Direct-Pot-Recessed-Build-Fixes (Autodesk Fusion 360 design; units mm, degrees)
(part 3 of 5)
sketch "Restore cam service opening after obsolete bore closure" plane through (23.9, 0, 0) normal (1, 0, 0) x axis (0, 0, -1)
  line L1 (-42.2047, 46.7373) -> (-43.8497, 47.5044)
  line L2 (-40.5875, 45.9133) -> (-42.2047, 46.7373)
  line L3 (-39, 45.0333) -> (-40.5875, 45.9133)
  line L4 (-37.4442, 44.0985) -> (-39, 45.0333)
  line L5 (-35.922, 43.11) -> (-37.4442, 44.0985)
  line L6 (-34.4352, 42.0689) -> (-35.922, 43.11)
  line L7 (-32.9856, 40.9766) -> (-34.4352, 42.0689)
  line L8 (-31.575, 39.8343) -> (-32.9856, 40.9766)
  line L9 (-30.2052, 38.6435) -> (-31.575, 39.8343)
  line L10 (-28.8778, 37.4057) -> (-30.2052, 38.6435)
  line L11 (-27.5943, 36.1222) -> (-28.8778, 37.4057)
  line L12 (-26.3565, 34.7948) -> (-27.5943, 36.1222)
  line L13 (-25.1657, 33.425) -> (-26.3565, 34.7948)
  line L14 (-24.0234, 32.0144) -> (-25.1657, 33.425)
  line L15 (-22.9311, 30.5648) -> (-24.0234, 32.0144)
  line L16 (-21.89, 29.078) -> (-22.9311, 30.5648)
  line L17 (-20.9015, 27.5558) -> (-21.89, 29.078)
  line L18 (-19.9667, 26) -> (-20.9015, 27.5558)
  line L19 (-19.0867, 24.4125) -> (-19.9667, 26)
  line L20 (-18.2627, 22.7953) -> (-19.0867, 24.4125)
  line L21 (-17.4956, 21.1503) -> (-18.2627, 22.7953)
  line L22 (-16.7864, 19.4795) -> (-17.4956, 21.1503)
  line L23 (-16.136, 17.785) -> (-16.7864, 19.4795)
  line L24 (-15.5451, 16.0689) -> (-16.136, 17.785)
  line L25 (-15.0144, 14.3331) -> (-15.5451, 16.0689)
  line L26 (-14.5446, 12.5799) -> (-15.0144, 14.3331)
  line L27 (-14.1363, 10.8114) -> (-14.5446, 12.5799)
  line L28 (-13.79, 9.0297) -> (-14.1363, 10.8114)
  line L29 (-13.5061, 7.237) -> (-13.79, 9.0297)
  line L30 (-13.2849, 5.4355) -> (-13.5061, 7.237)
  line L31 (-13.1267, 3.6273) -> (-13.2849, 5.4355)
  line L32 (-13.0317, 1.8148) -> (-13.1267, 3.6273)
  line L33 (-13, 0) -> (-13.0317, 1.8148)
  line L34 (-13.0317, -1.8148) -> (-13, 0)
  line L35 (-13.1267, -3.6273) -> (-13.0317, -1.8148)
  line L36 (-13.2849, -5.4355) -> (-13.1267, -3.6273)
  line L37 (-13.5061, -7.237) -> (-13.2849, -5.4355)
  line L38 (-13.79, -9.0297) -> (-13.5061, -7.237)
  line L39 (-14.1363, -10.8114) -> (-13.79, -9.0297)
  line L40 (-14.5446, -12.5799) -> (-14.1363, -10.8114)
  line L41 (-15.0144, -14.3331) -> (-14.5446, -12.5799)
  line L42 (-15.5451, -16.0689) -> (-15.0144, -14.3331)
  line L43 (-16.136, -17.785) -> (-15.5451, -16.0689)
  line L44 (-16.7864, -19.4795) -> (-16.136, -17.785)
  line L45 (-17.4956, -21.1503) -> (-16.7864, -19.4795)
  line L46 (-18.2627, -22.7953) -> (-17.4956, -21.1503)
  line L47 (-19.0867, -24.4125) -> (-18.2627, -22.7953)
  line L48 (-19.9667, -26) -> (-19.0867, -24.4125)
  line L49 (-20.9015, -27.5558) -> (-19.9667, -26)
  line L50 (-21.89, -29.078) -> (-20.9015, -27.5558)
  line L51 (-22.9311, -30.5648) -> (-21.89, -29.078)
  line L52 (-24.0234, -32.0144) -> (-22.9311, -30.5648)
  line L53 (-25.1657, -33.425) -> (-24.0234, -32.0144)
  line L54 (-26.3565, -34.7948) -> (-25.1657, -33.425)
  line L55 (-27.5943, -36.1222) -> (-26.3565, -34.7948)
  line L56 (-28.8778, -37.4057) -> (-27.5943, -36.1222)
  line L57 (-30.2052, -38.6435) -> (-28.8778, -37.4057)
  line L58 (-31.575, -39.8343) -> (-30.2052, -38.6435)
  line L59 (-32.9856, -40.9766) -> (-31.575, -39.8343)
  line L60 (-34.4352, -42.0689) -> (-32.9856, -40.9766)
  line L61 (-35.922, -43.11) -> (-34.4352, -42.0689)
  line L62 (-37.4442, -44.0985) -> (-35.922, -43.11)
  line L63 (-39, -45.0333) -> (-37.4442, -44.0985)
  line L64 (-40.5875, -45.9133) -> (-39, -45.0333)
  line L65 (-42.2047, -46.7373) -> (-40.5875, -45.9133)
  line L66 (-43.8497, -47.5044) -> (-42.2047, -46.7373)
  line L67 (-54.4248, -23.7522) -> (-43.8497, -47.5044)
  line L68 (-53.6024, -23.3686) -> (-54.4248, -23.7522)
  line L69 (-52.7937, -22.9566) -> (-53.6024, -23.3686)
  line L70 (-52, -22.5167) -> (-52.7937, -22.9566)
  line L71 (-51.2221, -22.0493) -> (-52, -22.5167)
  line L72 (-50.461, -21.555) -> (-51.2221, -22.0493)
  line L73 (-49.7176, -21.0344) -> (-50.461, -21.555)
  line L74 (-48.9928, -20.4883) -> (-49.7176, -21.0344)
  line L75 (-48.2875, -19.9172) -> (-48.9928, -20.4883)
  line L76 (-47.6026, -19.3218) -> (-48.2875, -19.9172)
  line L77 (-46.9389, -18.7028) -> (-47.6026, -19.3218)
  line L78 (-46.2972, -18.0611) -> (-46.9389, -18.7028)
  line L79 (-45.6782, -17.3974) -> (-46.2972, -18.0611)
  line L80 (-45.0828, -16.7125) -> (-45.6782, -17.3974)
  line L81 (-44.5117, -16.0072) -> (-45.0828, -16.7125)
  line L82 (-43.9656, -15.2824) -> (-44.5117, -16.0072)
  line L83 (-43.445, -14.539) -> (-43.9656, -15.2824)
  line L84 (-42.9507, -13.7779) -> (-43.445, -14.539)
  line L85 (-42.4833, -13) -> (-42.9507, -13.7779)
  line L86 (-42.0434, -12.2063) -> (-42.4833, -13)
  line L87 (-41.6314, -11.3976) -> (-42.0434, -12.2063)
  line L88 (-41.2478, -10.5752) -> (-41.6314, -11.3976)
  line L89 (-40.8932, -9.7398) -> (-41.2478, -10.5752)
  line L90 (-40.568, -8.8925) -> (-40.8932, -9.7398)
  line L91 (-40.2725, -8.0344) -> (-40.568, -8.8925)
  line L92 (-40.0072, -7.1666) -> (-40.2725, -8.0344)
  line L93 (-39.7723, -6.29) -> (-40.0072, -7.1666)
  line L94 (-39.5682, -5.4057) -> (-39.7723, -6.29)
  line L95 (-39.395, -4.5149) -> (-39.5682, -5.4057)
  line L96 (-39.253, -3.6185) -> (-39.395, -4.5149)
  line L97 (-39.1424, -2.7177) -> (-39.253, -3.6185)
  line L98 (-39.0633, -1.8137) -> (-39.1424, -2.7177)
  line L99 (-39.0158, -0.9074) -> (-39.0633, -1.8137)
  line L100 (-39, 0) -> (-39.0158, -0.9074)
  line L101 (-39.0158, 0.9074) -> (-39, 0)
  line L102 (-39.0633, 1.8137) -> (-39.0158, 0.9074)
  line L103 (-39.1424, 2.7177) -> (-39.0633, 1.8137)
  line L104 (-39.253, 3.6185) -> (-39.1424, 2.7177)
  line L105 (-39.395, 4.5149) -> (-39.253, 3.6185)
  line L106 (-39.5682, 5.4057) -> (-39.395, 4.5149)
  line L107 (-39.7723, 6.29) -> (-39.5682, 5.4057)
  line L108 (-40.0072, 7.1666) -> (-39.7723, 6.29)
  line L109 (-40.2725, 8.0344) -> (-40.0072, 7.1666)
  line L110 (-40.568, 8.8925) -> (-40.2725, 8.0344)
  line L111 (-40.8932, 9.7398) -> (-40.568, 8.8925)
  line L112 (-41.2478, 10.5752) -> (-40.8932, 9.7398)
  line L113 (-41.6314, 11.3976) -> (-41.2478, 10.5752)
  line L114 (-42.0434, 12.2063) -> (-41.6314, 11.3976)
  line L115 (-42.4833, 13) -> (-42.0434, 12.2063)
  line L116 (-42.9507, 13.7779) -> (-42.4833, 13)
  line L117 (-43.445, 14.539) -> (-42.9507, 13.7779)
  line L118 (-43.9656, 15.2824) -> (-43.445, 14.539)
  line L119 (-44.5117, 16.0072) -> (-43.9656, 15.2824)
  line L120 (-45.0828, 16.7125) -> (-44.5117, 16.0072)
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extrude "Extrude47" cut sketch "Restore cam service opening after obsolete bore closure" along normal blind 12.2
work_plane "WorkPlane48" AlongDistance -15.4 ExtraOffset 0
sketch "Fill former M5 stop nut pocket" plane through (-15.4, 0, 0) normal (1, 0, 0) x axis (0, 0, -1)
  circle C1 centre (-79.6754, -33.9652) radius 4.9
extrude "Extrude48" add sketch "Fill former M5 stop nut pocket" along normal blind 6.4
work_plane "WorkPlane49" AlongDistance -36 ExtraOffset 0
sketch "Fill former M5 stop bore" plane through (-36, 0, 0) normal (1, 0, 0) x axis (0, 0, -1)
  circle C1 centre (-79.6754, -33.9652) radius 2.71
extrude "Extrude49" add sketch "Fill former M5 stop bore" along normal blind 27
work_plane "WorkPlane50" AlongDistance -36.1 ExtraOffset 0
sketch "M3 stop reinforcement bore" plane through (-36.1, 0, 0) normal (1, 0, 0) x axis (0, 0, -1)
  circle C1 centre (-79.6754, -33.9652) radius 1.7
extrude "Extrude50" cut sketch "M3 stop reinforcement bore" along normal blind 27.2
work_plane "WorkPlane51" AlongDistance -13.5 ExtraOffset 0
sketch "Captive M3 locknut stop pocket" plane through (-13.5, 0, 0) normal (1, 0, 0) x axis (0, 0, -1)
  line L1 (-82.5754, -32.2908) -> (-79.6754, -30.6165)
  line L2 (-82.5754, -35.6395) -> (-82.5754, -32.2908)
  line L3 (-79.6754, -37.3138) -> (-82.5754, -35.6395)
  line L4 (-76.7754, -35.6395) -> (-79.6754, -37.3138)
  line L5 (-76.7754, -32.2908) -> (-76.7754, -35.6395)
  line L6 (-79.6754, -30.6165) -> (-76.7754, -32.2908)
extrude "Extrude51" cut sketch "Captive M3 locknut stop pocket" along normal blind 4.6
work_plane "WorkPlane52" AlongDistance -15.4 ExtraOffset 0
sketch "Fill former M5 stop nut pocket (1)" plane through (-15.4, 0, 0) normal (1, 0, 0) x axis (0, 0, -1)
  circle C1 centre (-79.6754, 33.9652) radius 4.9
extrude "Extrude52" add sketch "Fill former M5 stop nut pocket (1)" along normal blind 6.4
work_plane "WorkPlane53" AlongDistance -36 ExtraOffset 0
sketch "Fill former M5 stop bore (1)" plane through (-36, 0, 0) normal (1, 0, 0) x axis (0, 0, -1)
  circle C1 centre (-79.6754, 33.9652) radius 2.71
extrude "Extrude53" add sketch "Fill former M5 stop bore (1)" along normal blind 27
work_plane "WorkPlane54" AlongDistance -36.1 ExtraOffset 0
sketch "M3 stop reinforcement bore (1)" plane through (-36.1, 0, 0) normal (1, 0, 0) x axis (0, 0, -1)
  circle C1 centre (-79.6754, 33.9652) radius 1.7
extrude "Extrude54" cut sketch "M3 stop reinforcement bore (1)" along normal blind 27.2
work_plane "WorkPlane55" AlongDistance -13.5 ExtraOffset 0
sketch "Captive M3 locknut stop pocket (1)" plane through (-13.5, 0, 0) normal (1, 0, 0) x axis (0, 0, -1)
  line L1 (-82.5754, 35.6395) -> (-79.6754, 37.3138)
  line L2 (-82.5754, 32.2908) -> (-82.5754, 35.6395)
  line L3 (-79.6754, 30.6165) -> (-82.5754, 32.2908)
  line L4 (-76.7754, 32.2908) -> (-79.6754, 30.6165)
  line L5 (-76.7754, 35.6395) -> (-76.7754, 32.2908)
  line L6 (-79.6754, 37.3138) -> (-76.7754, 35.6395)
extrude "Extrude55" cut sketch "Captive M3 locknut stop pocket (1)" along normal blind 4.6
work_plane "WorkPlane56" AlongDistance -17.5 ExtraOffset 0
sketch "Recess M3 locknut to keep bolt inside stop" plane through (-17.5, 0, 0) normal (1, 0, 0) x axis (0, 0, -1)
  line L1 (-82.5754, -32.2908) -> (-79.6754, -30.6165)
  line L2 (-82.5754, -35.6395) -> (-82.5754, -32.2908)
  line L3 (-79.6754, -37.3138) -> (-82.5754, -35.6395)
  line L4 (-76.7754, -35.6395) -> (-79.6754, -37.3138)
  line L5 (-76.7754, -32.2908) -> (-76.7754, -35.6395)
  line L6 (-79.6754, -30.6165) -> (-76.7754, -32.2908)
extrude "Extrude56" cut sketch "Recess M3 locknut to keep bolt inside stop" along normal blind 4.01
work_plane "WorkPlane57" AlongDistance -17.5 ExtraOffset 0
sketch "Recess M3 locknut to keep bolt inside stop (1)" plane through (-17.5, 0, 0) normal (1, 0, 0) x axis (0, 0, -1)
  line L1 (-82.5754, 35.6395) -> (-79.6754, 37.3138)
  line L2 (-82.5754, 32.2908) -> (-82.5754, 35.6395)
  line L3 (-79.6754, 30.6165) -> (-82.5754, 32.2908)
  line L4 (-76.7754, 32.2908) -> (-79.6754, 30.6165)
  line L5 (-76.7754, 35.6395) -> (-76.7754, 32.2908)
  line L6 (-79.6754, 37.3138) -> (-76.7754, 35.6395)
extrude "Extrude57" cut sketch "Recess M3 locknut to keep bolt inside stop (1)" along normal blind 4.01
work_plane "WorkPlane6" AlongDistance -7.2 ExtraOffset 0
sketch "Upright socket roof 45 degrees" plane through (0, -7.2, 0) normal (0, 1, 0) x axis (1, 0, 0)
  line L1 (-7.2, -196) -> (0, -196)
  line L2 (0, -203.2) -> (-7.2, -196)
  line L3 (0, -196) -> (0, -203.2)
extrude "Extrude5" cut sketch "Upright socket roof 45 degrees" along normal blind 14.4
work_plane "WorkPlane8" AlongDistance -7.2 ExtraOffset 0
sketch "Upright socket roof 45 degrees" plane through (0, -7.2, 0) normal (0, 1, 0) x axis (1, 0, 0)
  line L1 (7.2, -196) -> (0, -196)
  line L2 (0, -203.2) -> (7.2, -196)
  line L3 (0, -196) -> (0, -203.2)
extrude "Extrude7" cut sketch "Upright socket roof 45 degrees" along normal blind 14.4
work_plane "WorkPlane58" AlongDistance -36 ExtraOffset 0
sketch "Stock M5x14 mounting seat Z64" plane through (-36, 0, 0) normal (1, 0, 0) x axis (0, 0, -1)
  line L1 (-63, -70) -> (-63, -95)
  line L2 (-64, -70) -> (-63, -70)
  line L3 (-64, -95) -> (-64, -70)
  line L4 (-63, -95) -> (-64, -95)
extrude "Extrude58" add sketch "Stock M5x14 mounting seat Z64" along normal blind 12
work_plane "WorkPlane59" AlongDistance 62.9 ExtraOffset 0
sketch "Continue rail clearance through new seat" plane through (0, 0, 62.9) normal (0, 0, 1) x axis (1, 0, 0)
  circle C1 centre (-30, -85) radius 2.7
extrude "Extrude59" cut sketch "Continue rail clearance through new seat" along normal blind 1.2
work_plane "WorkPlane1" AlongDistance 50 ExtraOffset 0
sketch "Rail M5x14 DIN912 (-30, -1)" plane through (0, 0, 50) normal (0, 0, 1) x axis (1, 0, 0)
  circle C1 centre (-30, -85) radius 2.5
extrude "Extrude1" new body sketch "Rail M5x14 DIN912 (-30, -1)" along normal blind 14 bodies "HARDWARE Rail M5x14 DIN912 (-30, -1)"
work_plane "WorkPlane2" AlongDistance 64 ExtraOffset 0
sketch "Button head" plane through (0, 0, 64) normal (0, 0, 1) x axis (1, 0, 0)
  circle C1 centre (-30, -85) radius 4.25
extrude "Extrude2" add sketch "Button head" along normal blind 5
work_plane "WorkPlane60" AlongDistance -36 ExtraOffset 0
sketch "Stock M5x14 mounting seat Z64 (1)" plane through (-36, 0, 0) normal (1, 0, 0) x axis (0, 0, -1)
  line L1 (-63, 95) -> (-63, 70)
  line L2 (-64, 95) -> (-63, 95)
  line L3 (-64, 70) -> (-64, 95)
  line L4 (-63, 70) -> (-64, 70)
extrude "Extrude60" add sketch "Stock M5x14 mounting seat Z64 (1)" along normal blind 12
work_plane "WorkPlane61" AlongDistance 62.9 ExtraOffset 0
sketch "Continue rail clearance through new seat (1)" plane through (0, 0, 62.9) normal (0, 0, 1) x axis (1, 0, 0)
  circle C1 centre (-30, 85) radius 2.7
extrude "Extrude61" cut sketch "Continue rail clearance through new seat (1)" along normal blind 1.2
work_plane "WorkPlane1" AlongDistance 50 ExtraOffset 0
sketch "Rail M5x14 DIN912 (-30, 1)" plane through (0, 0, 50) normal (0, 0, 1) x axis (1, 0, 0)
  circle C1 centre (-30, 85) radius 2.5
extrude "Extrude1" new body sketch "Rail M5x14 DIN912 (-30, 1)" along normal blind 14 bodies "HARDWARE Rail M5x14 DIN912 (-30, 1)"
work_plane "WorkPlane2" AlongDistance 64 ExtraOffset 0
sketch "Button head" plane through (0, 0, 64) normal (0, 0, 1) x axis (1, 0, 0)
  circle C1 centre (-30, 85) radius 4.25
extrude "Extrude2" add sketch "Button head" along normal blind 5
work_plane "WorkPlane62" AlongDistance -36 ExtraOffset 0
sketch "Close obsolete long pivot screw hole" plane through (-36, 0, 0) normal (1, 0, 0) x axis (0, 0, -1)
  circle C1 centre (-12, -35) radius 1.71
extrude "Extrude62" add sketch "Close obsolete long pivot screw hole" along normal blind 12
work_plane "WorkPlane63" AlongDistance -26 ExtraOffset 0
sketch "Blind captive printed pivot seat" plane through (-26, 0, 0) normal (1, 0, 0) x axis (0, 0, -1)
  circle C1 centre (-12, -35) radius 4.15
extrude "Extrude63" cut sketch "Blind captive printed pivot seat" along normal blind 2.1
work_plane "WorkPlane48" AlongDistance 24 ExtraOffset 0
sketch "Stock M5x14 mounting seat Z64" plane through (24, 0, 0) normal (1, 0, 0) x axis (0, 0, -1)
  line L1 (-63, -70) -> (-63, -95)
  line L2 (-64, -70) -> (-63, -70)
  line L3 (-64, -95) -> (-64, -70)
  line L4 (-63, -95) -> (-64, -95)
extrude "Extrude48" add sketch "Stock M5x14 mounting seat Z64" along normal blind 12
work_plane "WorkPlane49" AlongDistance 62.9 ExtraOffset 0
sketch "Continue rail clearance through new seat" plane through (0, 0, 62.9) normal (0, 0, 1) x axis (1, 0, 0)
  circle C1 centre (30, -85) radius 2.7
extrude "Extrude49" cut sketch "Continue rail clearance through new seat" along normal blind 1.2
work_plane "WorkPlane1" AlongDistance 50 ExtraOffset 0
sketch "Rail M5x14 DIN912 (30, -1)" plane through (0, 0, 50) normal (0, 0, 1) x axis (1, 0, 0)
  circle C1 centre (30, -85) radius 2.5
extrude "Extrude1" new body sketch "Rail M5x14 DIN912 (30, -1)" along normal blind 14 bodies "HARDWARE Rail M5x14 DIN912 (30, -1)"
work_plane "WorkPlane2" AlongDistance 64 ExtraOffset 0
sketch "Button head" plane through (0, 0, 64) normal (0, 0, 1) x axis (1, 0, 0)
  circle C1 centre (30, -85) radius 4.25
extrude "Extrude2" add sketch "Button head" along normal blind 5
work_plane "WorkPlane50" AlongDistance 24 ExtraOffset 0
sketch "Stock M5x14 mounting seat Z64 (1)" plane through (24, 0, 0) normal (1, 0, 0) x axis (0, 0, -1)
  line L1 (-63, 95) -> (-63, 70)
  line L2 (-64, 95) -> (-63, 95)
  line L3 (-64, 70) -> (-64, 95)
  line L4 (-63, 70) -> (-64, 70)
extrude "Extrude50" add sketch "Stock M5x14 mounting seat Z64 (1)" along normal blind 12
work_plane "WorkPlane51" AlongDistance 62.9 ExtraOffset 0
sketch "Continue rail clearance through new seat (1)" plane through (0, 0, 62.9) normal (0, 0, 1) x axis (1, 0, 0)
  circle C1 centre (30, 85) radius 2.7
extrude "Extrude51" cut sketch "Continue rail clearance through new seat (1)" along normal blind 1.2
work_plane "WorkPlane1" AlongDistance 50 ExtraOffset 0
sketch "Rail M5x14 DIN912 (30, 1)" plane through (0, 0, 50) normal (0, 0, 1) x axis (1, 0, 0)
  circle C1 centre (30, 85) radius 2.5
extrude "Extrude1" new body sketch "Rail M5x14 DIN912 (30, 1)" along normal blind 14 bodies "HARDWARE Rail M5x14 DIN912 (30, 1)"
work_plane "WorkPlane2" AlongDistance 64 ExtraOffset 0
sketch "Button head" plane through (0, 0, 64) normal (0, 0, 1) x axis (1, 0, 0)
  circle C1 centre (30, 85) radius 4.25
extrude "Extrude2" add sketch "Button head" along normal blind 5
work_plane "WorkPlane52" AlongDistance 24 ExtraOffset 0
sketch "Close obsolete long pivot screw hole" plane through (24, 0, 0) normal (1, 0, 0) x axis (0, 0, -1)
  circle C1 centre (-12, -35) radius 1.71
extrude "Extrude52" add sketch "Close obsolete long pivot screw hole" along normal blind 12
work_plane "WorkPlane53" AlongDistance 23.9 ExtraOffset 0
sketch "Blind captive printed pivot seat" plane through (23.9, 0, 0) normal (1, 0, 0) x axis (0, 0, -1)
  circle C1 centre (-12, -35) radius 4.15
extrude "Extrude53" cut sketch "Blind captive printed pivot seat" along normal blind 2.1
work_plane "WorkPlane1" AlongDistance -25.85 ExtraOffset 0
sketch "Captured axle 0.3 mm total end clearance" plane through (-25.85, 0, 0) normal (1, 0, 0) x axis (0, 0, -1)
  circle C1 centre (-12, -35) radius 4
extrude "Extrude1" new body sketch "Captured axle 0.3 mm total end clearance" along normal blind 51.7 bodies "P25 Captured printed pivot lower half"
work_plane "WorkPlane2" AlongDistance -26 ExtraOffset 0
sketch "Longitudinal flat print face" plane through (-26, 0, 0) normal (1, 0, 0) x axis (0, 0, -1)
  line L1 (-7, -30) -> (-7, -35)
  line L2 (-17, -30) -> (-7, -30)
  line L3 (-17, -35) -> (-17, -30)
  line L4 (-7, -35) -> (-17, -35)
extrude "Extrude2" cut sketch "Longitudinal flat print face" along normal blind 52
work_plane "WorkPlane1" AlongDistance -25.85 ExtraOffset 0
sketch "Captured axle 0.3 mm total end clearance" plane through (-25.85, 0, 0) normal (1, 0, 0) x axis (0, 0, -1)
  circle C1 centre (-12, -35) radius 4
extrude "Extrude1" new body sketch "Captured axle 0.3 mm total end clearance" along normal blind 51.7 bodies "P26 Captured printed pivot upper half"
work_plane "WorkPlane2" AlongDistance -26 ExtraOffset 0
sketch "Longitudinal flat print face" plane through (-26, 0, 0) normal (1, 0, 0) x axis (0, 0, -1)
  line L1 (-7, -35) -> (-7, -40)
  line L2 (-17, -35) -> (-7, -35)
  line L3 (-17, -40) -> (-17, -35)
  line L4 (-7, -40) -> (-17, -40)
extrude "Extrude2" cut sketch "Longitudinal flat print face" along normal blind 52
work_plane "WorkPlane9" AlongDistance 9 ExtraOffset 0
sketch "Recess for stocked M3x20 grip screw" plane through (9, 0, 0) normal (1, 0, 0) x axis (0, 0, -1)
  circle C1 centre (-180, 0) radius 3.1
extrude "Extrude8" cut sketch "Recess for stocked M3x20 grip screw" along normal blind 3.6
work_plane "WorkPlane1" AlongDistance -11 ExtraOffset 0
sketch "Grip M3x20 cap head 180" plane through (-11, 0, 0) normal (1, 0, 0) x axis (0, 0, -1)
  circle C1 centre (-180, 0) radius 1.5
extrude "Extrude1" new body sketch "Grip M3x20 cap head 180" along normal blind 20 bodies "HARDWARE Grip M3x20 cap head 180"
work_plane "WorkPlane2" AlongDistance 9 ExtraOffset 0
sketch "Button head" plane through (9, 0, 0) normal (1, 0, 0) x axis (0, 0, -1)
  circle C1 centre (-180, 0) radius 2.75
extrude "Extrude2" add sketch "Button head" along normal blind 3
work_plane "WorkPlane10" AlongDistance 9 ExtraOffset 0
sketch "Recess for stocked M3x20 grip screw (1)" plane through (9, 0, 0) normal (1, 0, 0) x axis (0, 0, -1)
  circle C1 centre (-190, 0) radius 3.1
extrude "Extrude9" cut sketch "Recess for stocked M3x20 grip screw (1)" along normal blind 3.6
work_plane "WorkPlane1" AlongDistance -11 ExtraOffset 0
sketch "Grip M3x20 cap head 190" plane through (-11, 0, 0) normal (1, 0, 0) x axis (0, 0, -1)
  circle C1 centre (-190, 0) radius 1.5
extrude "Extrude1" new body sketch "Grip M3x20 cap head 190" along normal blind 20 bodies "HARDWARE Grip M3x20 cap head 190"
work_plane "WorkPlane2" AlongDistance 9 ExtraOffset 0
sketch "Button head" plane through (9, 0, 0) normal (1, 0, 0) x axis (0, 0, -1)
  circle C1 centre (-190, 0) radius 2.75
extrude "Extrude2" add sketch "Button head" along normal blind 3
work_plane "WorkPlane64" AlongDistance -36.1 ExtraOffset 0
sketch "Stock M3x20 stop recessed cap head" plane through (-36.1, 0, 0) normal (1, 0, 0) x axis (0, 0, -1)
  circle C1 centre (-79.6754, -33.9652) radius 3.1
extrude "Extrude64" cut sketch "Stock M3x20 stop recessed cap head" along normal blind 4.6
work_plane "WorkPlane1" AlongDistance -31.5 ExtraOffset 0
sketch "Stop M3x20 cap head -1" plane through (-31.5, 0, 0) normal (1, 0, 0) x axis (0, 0, -1)
  circle C1 centre (-79.6754, -33.9652) radius 1.5
extrude "Extrude1" new body sketch "Stop M3x20 cap head -1" along normal blind 20 bodies "HARDWARE Stop M3x20 cap head -1"
work_plane "WorkPlane2" AlongDistance -34.5 ExtraOffset 0
sketch "Button head" plane through (-34.5, 0, 0) normal (1, 0, 0) x axis (0, 0, -1)
  circle C1 centre (-79.6754, -33.9652) radius 2.75
extrude "Extrude2" add sketch "Button head" along normal blind 3
work_plane "WorkPlane1" AlongDistance -17.5 ExtraOffset 0
sketch "Stop M3 plain captive nut -1" plane through (-17.5, 0, 0) normal (1, 0, 0) x axis (0, 0, -1)
  line L1 (-82.4254, -32.3774) -> (-79.6754, -30.7897)
  line L2 (-82.4254, -35.5529) -> (-82.4254, -32.3774)
  line L3 (-79.6754, -37.1406) -> (-82.4254, -35.5529)
  line L4 (-76.9254, -35.5529) -> (-79.6754, -37.1406)
  line L5 (-76.9254, -32.3774) -> (-76.9254, -35.5529)
  line L6 (-79.6754, -30.7897) -> (-76.9254, -32.3774)
extrude "Extrude1" new body sketch "Stop M3 plain captive nut -1" along normal blind 2.4 bodies "HARDWARE Stop M3 plain captive nut -1"
work_plane "WorkPlane2" AlongDistance -17.6 ExtraOffset 0
sketch "Thread envelope" plane through (-17.6, 0, 0) normal (1, 0, 0) x axis (0, 0, -1)
  circle C1 centre (-79.6754, -33.9652) radius 1.5
extrude "Extrude2" cut sketch "Thread envelope" along normal blind 2.6
work_plane "WorkPlane65" AlongDistance -36.1 ExtraOffset 0
sketch "Stock M3x20 stop recessed cap head (1)" plane through (-36.1, 0, 0) normal (1, 0, 0) x axis (0, 0, -1)
  circle C1 centre (-79.6754, 33.9652) radius 3.1
extrude "Extrude65" cut sketch "Stock M3x20 stop recessed cap head (1)" along normal blind 4.6
work_plane "WorkPlane1" AlongDistance -31.5 ExtraOffset 0
sketch "Stop M3x20 cap head 1" plane through (-31.5, 0, 0) normal (1, 0, 0) x axis (0, 0, -1)
  circle C1 centre (-79.6754, 33.9652) radius 1.5
extrude "Extrude1" new body sketch "Stop M3x20 cap head 1" along normal blind 20 bodies "HARDWARE Stop M3x20 cap head 1"
work_plane "WorkPlane2" AlongDistance -34.5 ExtraOffset 0
sketch "Button head" plane through (-34.5, 0, 0) normal (1, 0, 0) x axis (0, 0, -1)
  circle C1 centre (-79.6754, 33.9652) radius 2.75
extrude "Extrude2" add sketch "Button head" along normal blind 3
work_plane "WorkPlane1" AlongDistance -17.5 ExtraOffset 0
sketch "Stop M3 plain captive nut 1" plane through (-17.5, 0, 0) normal (1, 0, 0) x axis (0, 0, -1)
  line L1 (-82.4254, 35.5529) -> (-79.6754, 37.1406)
  line L2 (-82.4254, 32.3774) -> (-82.4254, 35.5529)
  line L3 (-79.6754, 30.7897) -> (-82.4254, 32.3774)
  line L4 (-76.9254, 32.3774) -> (-79.6754, 30.7897)
  line L5 (-76.9254, 35.5529) -> (-76.9254, 32.3774)
  line L6 (-79.6754, 37.1406) -> (-76.9254, 35.5529)
extrude "Extrude1" new body sketch "Stop M3 plain captive nut 1" along normal blind 2.4 bodies "HARDWARE Stop M3 plain captive nut 1"
work_plane "WorkPlane2" AlongDistance -17.6 ExtraOffset 0
sketch "Thread envelope" plane through (-17.6, 0, 0) normal (1, 0, 0) x axis (0, 0, -1)
  circle C1 centre (-79.6754, 33.9652) radius 1.5
extrude "Extrude2" cut sketch "Thread envelope" along normal blind 2.6
work_plane "WorkPlane10" AlongDistance 7 ExtraOffset 0
sketch "Bearing inner race support pad" plane through (7, 0, 0) normal (1, 0, 0) x axis (0, 0, -1)
  circle C1 centre (-12, 0) radius 2.4
extrude "Extrude10" add sketch "Bearing inner race support pad" along normal blind 1
work_plane "WorkPlane11" AlongDistance 6.9 ExtraOffset 0
sketch "Preserve roller screw clearance" plane through (6.9, 0, 0) normal (1, 0, 0) x axis (0, 0, -1)
  circle C1 centre (-12, 0) radius 1.7
extrude "Extrude11" cut sketch "Preserve roller screw clearance" along normal blind 1.2
work_plane "WorkPlane12" AlongDistance 16 ExtraOffset 0
sketch "Bearing inner race support pad (1)" plane through (16, 0, 0) normal (1, 0, 0) x axis (0, 0, -1)
  circle C1 centre (-12, 0) radius 2.4
extrude "Extrude12" add sketch "Bearing inner race support pad (1)" along normal blind 1
work_plane "WorkPlane13" AlongDistance 15.9 ExtraOffset 0
sketch "Preserve roller screw clearance (1)" plane through (15.9, 0, 0) normal (1, 0, 0) x axis (0, 0, -1)
  circle C1 centre (-12, 0) radius 1.7
extrude "Extrude13" cut sketch "Preserve roller screw clearance (1)" along normal blind 1.2
work_plane "WorkPlane1" AlongDistance 8 ExtraOffset 0
sketch "Stock 623ZZ envelope 3x10x4" plane through (8, 0, 0) normal (1, 0, 0) x axis (0, 0, -1)
  circle C1 centre (-12, 0) radius 5
extrude "Extrude1" new body sketch "Stock 623ZZ envelope 3x10x4" along normal blind 4 bodies "HARDWARE 623ZZ roller bearing at 8"
work_plane "WorkPlane2" AlongDistance 7.9 ExtraOffset 0
sketch "Bearing inner race bore" plane through (7.9, 0, 0) normal (1, 0, 0) x axis (0, 0, -1)
  circle C1 centre (-12, 0) radius 1.5
extrude "Extrude2" cut sketch "Bearing inner race bore" along normal blind 4.2
work_plane "WorkPlane1" AlongDistance 12 ExtraOffset 0
sketch "Stock 623ZZ envelope 3x10x4" plane through (12, 0, 0) normal (1, 0, 0) x axis (0, 0, -1)
  circle C1 centre (-12, 0) radius 5
extrude "Extrude1" new body sketch "Stock 623ZZ envelope 3x10x4" along normal blind 4 bodies "HARDWARE 623ZZ roller bearing at 12"
work_plane "WorkPlane2" AlongDistance 11.9 ExtraOffset 0
sketch "Bearing inner race bore" plane through (11.9, 0, 0) normal (1, 0, 0) x axis (0, 0, -1)
  circle C1 centre (-12, 0) radius 1.5
extrude "Extrude2" cut sketch "Bearing inner race bore" along normal blind 4.2
work_plane "WorkPlane45" AlongDistance 38 ExtraOffset 0
sketch "Close former long guide bore" plane through (0, 0, 38) normal (0, 0, 1) x axis (1, 0, 0)
  circle C1 centre (5, -55) radius 1.71
extrude "Extrude45" add sketch "Close former long guide bore" along normal blind 21
work_plane "WorkPlane46" AlongDistance 38 ExtraOffset 0
sketch "Close former long guide bore (1)" plane through (0, 0, 38) normal (0, 0, 1) x axis (1, 0, 0)
  circle C1 centre (19, -55) radius 1.71
extrude "Extrude46" add sketch "Close former long guide bore (1)" along normal blind 21
work_plane "WorkPlane47" AlongDistance 38 ExtraOffset 0
sketch "Close obsolete M4 nut pocket" plane through (0, 0, 38) normal (0, 0, 1) x axis (1, 0, 0)
  line L1 (14.1362, -51.3) -> (16.2724, -55)
  line L2 (9.8638, -51.3) -> (14.1362, -51.3)
  line L3 (7.7276, -55) -> (9.8638, -51.3)
  line L4 (9.8638, -58.7) -> (7.7276, -55)
  line L5 (14.1362, -58.7) -> (9.8638, -58.7)
  line L6 (16.2724, -55) -> (14.1362, -58.7)
extrude "Extrude47" add sketch "Close obsolete M4 nut pocket" along normal blind 3.5
work_plane "WorkPlane48" AlongDistance 38 ExtraOffset 0
sketch "Close obsolete M4 adjuster passage" plane through (0, 0, 38) normal (0, 0, 1) x axis (1, 0, 0)
  circle C1 centre (12, -55) radius 2.21
extrude "Extrude48" add sketch "Close obsolete M4 adjuster passage" along normal blind 21
work_plane "WorkPlane49" AlongDistance 37.9 ExtraOffset 0
sketch "M3 preload adjuster passage" plane through (0, 0, 37.9) normal (0, 0, 1) x axis (1, 0, 0)
  circle C1 centre (12, -55) radius 1.7
extrude "Extrude49" cut sketch "M3 preload adjuster passage" along normal blind 21.2
work_plane "WorkPlane50" AlongDistance 37.9 ExtraOffset 0
sketch "M3 preload insert from spring side" plane through (0, 0, 37.9) normal (0, 0, 1) x axis (1, 0, 0)
  circle C1 centre (12, -55) radius 2
extrude "Extrude50" cut sketch "M3 preload insert from spring side" along normal blind 6.9
work_plane "WorkPlane51" AlongDistance 55 ExtraOffset 0
sketch "Recessed preload head and limiter access" plane through (0, 0, 55) normal (0, 0, 1) x axis (1, 0, 0)
  circle C1 centre (12, -55) radius 3.4
extrude "Extrude51" cut sketch "Recessed preload head and limiter access" along normal blind 4.1
work_plane "WorkPlane52" AlongDistance 37.9 ExtraOffset 0
sketch "Short guide M3 insert from underside" plane through (0, 0, 37.9) normal (0, 0, 1) x axis (1, 0, 0)
  circle C1 centre (4, -55) radius 2
extrude "Extrude52" cut sketch "Short guide M3 insert from underside" along normal blind 6.9
work_plane "WorkPlane1" AlongDistance 32 ExtraOffset 0
sketch "Short compression sleeve" plane through (0, 0, 32) normal (0, 0, 1) x axis (1, 0, 0)
  circle C1 centre (4, -55) radius 2.5
extrude "Extrude1" new body sketch "Short compression sleeve" along normal blind 6 bodies "P27 Printed guide sleeve 4"
work_plane "WorkPlane2" AlongDistance 31.9 ExtraOffset 0
sketch "Guide screw bore" plane through (0, 0, 31.9) normal (0, 0, 1) x axis (1, 0, 0)
  circle C1 centre (4, -55) radius 1.65
extrude "Extrude2" cut sketch "Guide screw bore" along normal blind 6.2
work_plane "WorkPlane1" AlongDistance 32 ExtraOffset 0
sketch "Cup guide M3x12 4" plane through (0, 0, 32) normal (0, 0, 1) x axis (1, 0, 0)
  circle C1 centre (4, -55) radius 1.5
extrude "Extrude1" new body sketch "Cup guide M3x12 4" along normal blind 12 bodies "HARDWARE Cup guide M3x12 4"
work_plane "WorkPlane2" AlongDistance 29 ExtraOffset 0
sketch "Button head" plane through (0, 0, 29) normal (0, 0, 1) x axis (1, 0, 0)
  circle C1 centre (4, -55) radius 2.75
extrude "Extrude2" add sketch "Button head" along normal blind 3
work_plane "WorkPlane53" AlongDistance 37.9 ExtraOffset 0
sketch "Short guide M3 insert from underside (1)" plane through (0, 0, 37.9) normal (0, 0, 1) x axis (1, 0, 0)
  circle C1 centre (20, -55) radius 2
extrude "Extrude53" cut sketch "Short guide M3 insert from underside (1)" along normal blind 6.9
work_plane "WorkPlane1" AlongDistance 32 ExtraOffset 0
sketch "Short compression sleeve" plane through (0, 0, 32) normal (0, 0, 1) x axis (1, 0, 0)
  circle C1 centre (20, -55) radius 2.5
extrude "Extrude1" new body sketch "Short compression sleeve" along normal blind 6 bodies "P27 Printed guide sleeve 20"
work_plane "WorkPlane2" AlongDistance 31.9 ExtraOffset 0
sketch "Guide screw bore" plane through (0, 0, 31.9) normal (0, 0, 1) x axis (1, 0, 0)
  circle C1 centre (20, -55) radius 1.65
extrude "Extrude2" cut sketch "Guide screw bore" along normal blind 6.2
work_plane "WorkPlane1" AlongDistance 32 ExtraOffset 0
sketch "Cup guide M3x12 20" plane through (0, 0, 32) normal (0, 0, 1) x axis (1, 0, 0)
  circle C1 centre (20, -55) radius 1.5
extrude "Extrude1" new body sketch "Cup guide M3x12 20" along normal blind 12 bodies "HARDWARE Cup guide M3x12 20"
work_plane "WorkPlane2" AlongDistance 29 ExtraOffset 0
sketch "Button head" plane through (0, 0, 29) normal (0, 0, 1) x axis (1, 0, 0)
  circle C1 centre (20, -55) radius 2.75
extrude "Extrude2" add sketch "Button head" along normal blind 3
work_plane "WorkPlane1" AlongDistance 0.2 ExtraOffset 0
sketch "Wide stock spring seat" plane through (0.2, 0, 0) normal (1, 0, 0) x axis (0, 0, -1)
  line L1 (-35, -49) -> (-35, -61)
  line L2 (-37, -49) -> (-35, -49)
  line L3 (-37, -61) -> (-37, -49)
  line L4 (-35, -61) -> (-37, -61)
extrude "Extrude1" new body sketch "Wide stock spring seat" along normal blind 23.6 bodies "P14 Captive spring cup for 9 mm spring"
work_plane "WorkPlane2" AlongDistance 29 ExtraOffset 0
sketch "Provisional 6 mm spring pilot" plane through (0, 0, 29) normal (0, 0, 1) x axis (1, 0, 0)
  circle C1 centre (12, -55) radius 3
extrude "Extrude2" add sketch "Provisional 6 mm spring pilot" along normal blind 6
work_plane "WorkPlane3" AlongDistance 34.9 ExtraOffset 0
sketch "Printed guide running clearance" plane through (0, 0, 34.9) normal (0, 0, 1) x axis (1, 0, 0)
  circle C1 centre (4, -55) radius 2.7
extrude "Extrude3" cut sketch "Printed guide running clearance" along normal blind 2.2
work_plane "WorkPlane4" AlongDistance 34.9 ExtraOffset 0
sketch "Printed guide running clearance (1)" plane through (0, 0, 34.9) normal (0, 0, 1) x axis (1, 0, 0)
  circle C1 centre (20, -55) radius 2.7
extrude "Extrude4" cut sketch "Printed guide running clearance (1)" along normal blind 2.2
work_plane "WorkPlane1" AlongDistance 55 ExtraOffset 0
sketch "Preserve one mm additional compression limit" plane through (0, 0, 55) normal (0, 0, 1) x axis (1, 0, 0)
  circle C1 centre (12, -55) radius 3.2
extrude "Extrude1" new body sketch "Preserve one mm additional compression limit" along normal blind 2 bodies "P15 Recessed preload limit collar 1 mm"
work_plane "WorkPlane2" AlongDistance 54.9 ExtraOffset 0
sketch "M3 adjuster clearance" plane through (0, 0, 54.9) normal (0, 0, 1) x axis (1, 0, 0)
  circle C1 centre (12, -55) radius 1.7
extrude "Extrude2" cut sketch "M3 adjuster clearance" along normal blind 2.2
work_plane "WorkPlane1" AlongDistance 37 ExtraOffset 0
sketch "Preload M3x20 cap head" plane through (0, 0, 37) normal (0, 0, 1) x axis (1, 0, 0)
  circle C1 centre (12, -55) radius 1.5
extrude "Extrude1" new body sketch "Preload M3x20 cap head" along normal blind 20 bodies "HARDWARE Preload M3x20 cap head"
work_plane "WorkPlane2" AlongDistance 57 ExtraOffset 0
sketch "Button head" plane through (0, 0, 57) normal (0, 0, 1) x axis (1, 0, 0)
  circle C1 centre (12, -55) radius 2.75
extrude "Extrude2" add sketch "Button head" along normal blind 3
work_plane "WorkPlane1" AlongDistance 18 ExtraOffset 0
sketch "Provisional stock spring installed envelope" plane through (0, 0, 18) normal (0, 0, 1) x axis (1, 0, 0)
  circle C1 centre (12, -55) radius 4.5
extrude "Extrude1" new body sketch "Provisional stock spring installed envelope" along normal blind 17 bodies "REFERENCE Stock spring OD9 wire1 free20 - rate and solid height assumed"
work_plane "WorkPlane2" AlongDistance 17.9 ExtraOffset 0
sketch "Stock spring nominal ID7" plane through (0, 0, 17.9) normal (0, 0, 1) x axis (1, 0, 0)
  circle C1 centre (12, -55) radius 3.5
extrude "Extrude2" cut sketch "Stock spring nominal ID7" along normal blind 17.2
work_plane "WorkPlane9" AlongDistance 40.35 ExtraOffset 0
sketch "Remove separate input hub drive stub" plane through (40.35, 0, 0) normal (1, 0, 0) x axis (0, 0, -1)
  line L1 (-53, 12) -> (-53, -12)
  line L2 (-79, 12) -> (-53, 12)
  line L3 (-79, -12) -> (-79, 12)
  line L4 (-53, -12) -> (-79, -12)
extrude "Extrude9" cut sketch "Remove separate input hub drive stub" along normal blind 10.15
work_plane "WorkPlane10" AlongDistance 40.35 ExtraOffset 0
sketch "Integrated compact Oldham input tongue" plane through (40.35, 0, 0) normal (1, 0, 0) x axis (0, 0, -1)
  line L1 (-63, 6.5) -> (-63, -8)
  line L2 (-67, 6.5) -> (-63, 6.5)
  line L3 (-67, -8) -> (-67, 6.5)
  line L4 (-63, -8) -> (-67, -8)
extrude "Extrude10" add sketch "Integrated compact Oldham input tongue" along normal blind 3
work_plane "WorkPlane54" AlongDistance 36 ExtraOffset 0
sketch "Remove long sensor carriage supports" plane through (36, 0, 0) normal (1, 0, 0) x axis (0, 0, -1)
  line L1 (-46, 34) -> (-46, -34)
  line L2 (-84, 34) -> (-46, 34)
  line L3 (-84, -34) -> (-84, 34)
  line L4 (-46, -34) -> (-84, -34)
extrude "Extrude54" cut sketch "Remove long sensor carriage supports" along normal blind 44.1
work_plane "WorkPlane55" AlongDistance 36 ExtraOffset 0
sketch "Compact sensor support" plane through (36, 0, 0) normal (1, 0, 0) x axis (0, 0, -1)
  line L1 (-49, -18) -> (-49, -28)
  line L2 (-81, -18) -> (-49, -18)
  line L3 (-81, -28) -> (-81, -18)
  line L4 (-49, -28) -> (-81, -28)
extrude "Extrude55" add sketch "Compact sensor support" along normal blind 30.15
work_plane "WorkPlane56" AlongDistance -28.1 ExtraOffset 0
sketch "Compact carriage M3 insert" plane through (0, -28.1, 0) normal (0, 1, 0) x axis (1, 0, 0)
  circle C1 centre (60.15, -65) radius 2
extrude "Extrude56" cut sketch "Compact carriage M3 insert" along normal blind 6.8
work_plane "WorkPlane57" AlongDistance 36 ExtraOffset 0
sketch "Compact sensor support (1)" plane through (36, 0, 0) normal (1, 0, 0) x axis (0, 0, -1)
  line L1 (-49, 28) -> (-49, 18)
  line L2 (-81, 28) -> (-49, 28)
  line L3 (-81, 18) -> (-81, 28)
  line L4 (-49, 18) -> (-81, 18)
extrude "Extrude57" add sketch "Compact sensor support (1)" along normal blind 30.15
work_plane "WorkPlane58" AlongDistance 21.3 ExtraOffset 0
sketch "Compact carriage M3 insert (1)" plane through (0, 21.3, 0) normal (0, 1, 0) x axis (1, 0, 0)
  circle C1 centre (60.15, -65) radius 2
extrude "Extrude58" cut sketch "Compact carriage M3 insert (1)" along normal blind 6.8
work_plane "WorkPlane1" AlongDistance 66.15 ExtraOffset 0
sketch "Replaceable compact sensor panel" plane through (66.15, 0, 0) normal (1, 0, 0) x axis (0, 0, -1)
  line L1 (-46, 33) -> (-46, -33)
  line L2 (-84, 33) -> (-46, 33)
  line L3 (-84, -33) -> (-84, 33)
  line L4 (-46, -33) -> (-84, -33)
extrude "Extrude1" new body sketch "Replaceable compact sensor panel" along normal blind 3 bodies "P16 Compact adjustable RK097 mount"
work_plane "WorkPlane2" AlongDistance 54.15 ExtraOffset 0
sketch "Compact sliding ear" plane through (54.15, 0, 0) normal (1, 0, 0) x axis (0, 0, -1)
  line L1 (-58, -28) -> (-58, -33)
  line L2 (-72, -28) -> (-58, -28)
  line L3 (-72, -33) -> (-72, -28)
  line L4 (-58, -33) -> (-72, -33)
extrude "Extrude2" add sketch "Compact sliding ear" along normal blind 12.1
work_plane "WorkPlane3" AlongDistance -33.1 ExtraOffset 0
sketch "Axial adjustment slot" plane through (0, -33.1, 0) normal (0, 1, 0) x axis (1, 0, 0)
  line L1 (65.15, -63.3) -> (55.15, -63.3)
  line L2 (65.15, -66.7) -> (65.15, -63.3)
  line L3 (55.15, -66.7) -> (65.15, -66.7)
  line L4 (55.15, -63.3) -> (55.15, -66.7)
extrude "Extrude3" cut sketch "Axial adjustment slot" along normal blind 5.2
work_plane "WorkPlane4" AlongDistance -33.1 ExtraOffset 0
sketch "Rounded slot end" plane through (0, -33.1, 0) normal (0, 1, 0) x axis (1, 0, 0)
  circle C1 centre (55.15, -65) radius 1.7
extrude "Extrude4" cut sketch "Rounded slot end" along normal blind 5.2
work_plane "WorkPlane5" AlongDistance -33.1 ExtraOffset 0
sketch "Rounded slot end (1)" plane through (0, -33.1, 0) normal (0, 1, 0) x axis (1, 0, 0)
  circle C1 centre (65.15, -65) radius 1.7
extrude "Extrude5" cut sketch "Rounded slot end (1)" along normal blind 5.2
work_plane "WorkPlane1" AlongDistance -33 ExtraOffset 0
sketch "Compact carriage M3x12 -1" plane through (0, -33, 0) normal (0, 1, 0) x axis (1, 0, 0)
  circle C1 centre (60.15, -65) radius 1.5
extrude "Extrude1" new body sketch "Compact carriage M3x12 -1" along normal blind 12 bodies "HARDWARE Compact carriage M3x12 -1"
work_plane "WorkPlane2" AlongDistance -36 ExtraOffset 0
sketch "Button head" plane through (0, -36, 0) normal (0, 1, 0) x axis (1, 0, 0)
  circle C1 centre (60.15, -65) radius 2.75
extrude "Extrude2" add sketch "Button head" along normal blind 3
work_plane "WorkPlane6" AlongDistance 54.15 ExtraOffset 0
sketch "Compact sliding ear (1)" plane through (54.15, 0, 0) normal (1, 0, 0) x axis (0, 0, -1)
  line L1 (-58, 33) -> (-58, 28)
  line L2 (-72, 33) -> (-58, 33)
  line L3 (-72, 28) -> (-72, 33)
  line L4 (-58, 28) -> (-72, 28)
extrude "Extrude6" add sketch "Compact sliding ear (1)" along normal blind 12.1
work_plane "WorkPlane7" AlongDistance 27.9 ExtraOffset 0
sketch "Axial adjustment slot (1)" plane through (0, 27.9, 0) normal (0, 1, 0) x axis (1, 0, 0)
  line L1 (65.15, -63.3) -> (55.15, -63.3)
  line L2 (65.15, -66.7) -> (65.15, -63.3)
  line L3 (55.15, -66.7) -> (65.15, -66.7)
  line L4 (55.15, -63.3) -> (55.15, -66.7)
extrude "Extrude7" cut sketch "Axial adjustment slot (1)" along normal blind 5.2
work_plane "WorkPlane8" AlongDistance 27.9 ExtraOffset 0
sketch "Rounded slot end (2)" plane through (0, 27.9, 0) normal (0, 1, 0) x axis (1, 0, 0)
  circle C1 centre (55.15, -65) radius 1.7
extrude "Extrude8" cut sketch "Rounded slot end (2)" along normal blind 5.2
work_plane "WorkPlane9" AlongDistance 27.9 ExtraOffset 0
sketch "Rounded slot end (3)" plane through (0, 27.9, 0) normal (0, 1, 0) x axis (1, 0, 0)
  circle C1 centre (65.15, -65) radius 1.7
extrude "Extrude9" cut sketch "Rounded slot end (3)" along normal blind 5.2
work_plane "WorkPlane1" AlongDistance 21 ExtraOffset 0
sketch "Compact carriage M3x12 1" plane through (0, 21, 0) normal (0, 1, 0) x axis (1, 0, 0)
  circle C1 centre (60.15, -65) radius 1.5
extrude "Extrude1" new body sketch "Compact carriage M3x12 1" along normal blind 12 bodies "HARDWARE Compact carriage M3x12 1"
work_plane "WorkPlane2" AlongDistance 33 ExtraOffset 0
sketch "Button head" plane through (0, 33, 0) normal (0, 1, 0) x axis (1, 0, 0)
  circle C1 centre (60.15, -65) radius 2.75
extrude "Extrude2" add sketch "Button head" along normal blind 3
work_plane "WorkPlane10" AlongDistance 66.05 ExtraOffset 0
sketch "Provisional M7 sensor bushing opening" plane through (66.05, 0, 0) normal (1, 0, 0) x axis (0, 0, -1)
  circle C1 centre (-65, 0) radius 3.6
extrude "Extrude10" cut sketch "Provisional M7 sensor bushing opening" along normal blind 3.2
work_plane "WorkPlane11" AlongDistance 66.05 ExtraOffset 0
sketch "Sensor body retention option" plane through (66.05, 0, 0) normal (1, 0, 0) x axis (0, 0, -1)
  line L1 (-59, -7) -> (-59, -9)
  line L2 (-71, -7) -> (-59, -7)
  line L3 (-71, -9) -> (-71, -7)
  line L4 (-59, -9) -> (-71, -9)
extrude "Extrude11" cut sketch "Sensor body retention option" along normal blind 3.2
work_plane "WorkPlane12" AlongDistance 66.05 ExtraOffset 0
sketch "Sensor body retention option (1)" plane through (66.05, 0, 0) normal (1, 0, 0) x axis (0, 0, -1)
  line L1 (-59, 9) -> (-59, 7)
  line L2 (-71, 9) -> (-59, 9)
  line L3 (-71, 7) -> (-71, 9)
  line L4 (-59, 7) -> (-71, 7)
extrude "Extrude12" cut sketch "Sensor body retention option (1)" along normal blind 3.2
work_plane "WorkPlane1" AlongDistance 41 ExtraOffset 0
sketch "Compact Oldham disc" plane through (41, 0, 0) normal (1, 0, 0) x axis (0, 0, -1)
  circle C1 centre (-65, 0) radius 12
extrude "Extrude1" new body sketch "Compact Oldham disc" along normal blind 8 bodies "P18 Compact floating coupling disc"
work_plane "WorkPlane2" AlongDistance 40.9 ExtraOffset 0
sketch "Input groove 4.2 mm" plane through (40.9, 0, 0) normal (1, 0, 0) x axis (0, 0, -1)
  line L1 (-62.9, 13) -> (-62.9, -13)
  line L2 (-67.1, 13) -> (-62.9, 13)
  line L3 (-67.1, -13) -> (-67.1, 13)
  line L4 (-62.9, -13) -> (-67.1, -13)
extrude "Extrude2" cut sketch "Input groove 4.2 mm" along normal blind 2.9
work_plane "WorkPlane3" AlongDistance 46.2 ExtraOffset 0
sketch "Output groove 4.2 mm" plane through (46.2, 0, 0) normal (1, 0, 0) x axis (0, 0, -1)
  line L1 (-52, 2.1) -> (-52, -2.1)
  line L2 (-78, 2.1) -> (-52, 2.1)
  line L3 (-78, -2.1) -> (-78, 2.1)
  line L4 (-52, -2.1) -> (-78, -2.1)
extrude "Extrude3" cut sketch "Output groove 4.2 mm" along normal blind 2.9
work_plane "WorkPlane1" AlongDistance 49.65 ExtraOffset 0
sketch "Single split output hub" plane through (49.65, 0, 0) normal (1, 0, 0) x axis (0, 0, -1)
  circle C1 centre (-65, 0) radius 7
extrude "Extrude1" new body sketch "Single split output hub" along normal blind 9 bodies "P19 Compact one-piece sensor clamp"
work_plane "WorkPlane2" AlongDistance 49.65 ExtraOffset 0
sketch "One-screw clamp boss" plane through (49.65, 0, 0) normal (1, 0, 0) x axis (0, 0, -1)
  line L1 (-69, 9) -> (-69, -9)
  line L2 (-78, 9) -> (-69, 9)
  line L3 (-78, -9) -> (-78, 9)
  line L4 (-69, -9) -> (-78, -9)
extrude "Extrude2" add sketch "One-screw clamp boss" along normal blind 9
work_plane "WorkPlane3" AlongDistance 46.65 ExtraOffset 0
sketch "Output drive prongs" plane through (46.65, 0, 0) normal (1, 0, 0) x axis (0, 0, -1)
  line L1 (-57, 2) -> (-57, -2)
  line L2 (-73, 2) -> (-57, 2)
  line L3 (-73, -2) -> (-73, 2)
  line L4 (-57, -2) -> (-73, -2)
extrude "Extrude3" add sketch "Output drive prongs" along normal blind 3.1
work_plane "WorkPlane4" AlongDistance 46.55 ExtraOffset 0
sketch "Provisional 6 mm sensor through socket" plane through (46.55, 0, 0) normal (1, 0, 0) x axis (0, 0, -1)
  circle C1 centre (-65, 0) radius 3.1
extrude "Extrude4" cut sketch "Provisional 6 mm sensor through socket" along normal blind 12.2
work_plane "WorkPlane5" AlongDistance 46.55 ExtraOffset 0
sketch "Elastic clamp split" plane through (46.55, 0, 0) normal (1, 0, 0) x axis (0, 0, -1)
  line L1 (-65, 0.2) -> (-65, -0.2)
  line L2 (-79, 0.2) -> (-65, 0.2)
  line L3 (-79, -0.2) -> (-79, 0.2)
  line L4 (-65, -0.2) -> (-79, -0.2)
extrude "Extrude5" cut sketch "Elastic clamp split" along normal blind 12.2
work_plane "WorkPlane6" AlongDistance -9.1 ExtraOffset 0
sketch "Accessible CNC Kitchen insert pocket" plane through (0, -9.1, 0) normal (0, 1, 0) x axis (1, 0, 0)
  circle C1 centre (54.15, -73) radius 2
extrude "Extrude6" cut sketch "Accessible CNC Kitchen insert pocket" along normal blind 9
work_plane "WorkPlane7" AlongDistance 0.1 ExtraOffset 0
sketch "Clamp screw clearance" plane through (0, 0.1, 0) normal (0, 1, 0) x axis (1, 0, 0)
  circle C1 centre (54.15, -73) radius 1.7
extrude "Extrude7" cut sketch "Clamp screw clearance" along normal blind 9
work_plane "WorkPlane1" AlongDistance -7 ExtraOffset 0
sketch "Compact sensor clamp M3x16" plane through (0, -7, 0) normal (0, 1, 0) x axis (1, 0, 0)
  circle C1 centre (54.15, -73) radius 1.5
extrude "Extrude1" new body sketch "Compact sensor clamp M3x16" along normal blind 16 bodies "HARDWARE Compact sensor clamp M3x16"
work_plane "WorkPlane2" AlongDistance 9 ExtraOffset 0
sketch "Button head" plane through (0, 9, 0) normal (0, 1, 0) x axis (1, 0, 0)
  circle C1 centre (54.15, -73) radius 2.75
extrude "Extrude2" add sketch "Button head" along normal blind 3
work_plane "WorkPlane59" AlongDistance 36 ExtraOffset 0
sketch "Restore cam service path beneath compact rails" plane through (36, 0, 0) normal (1, 0, 0) x axis (0, 0, -1)
  line L1 (-48.9, -18) -> (-48.9, -28)
  line L2 (-56, -18) -> (-48.9, -18)
  line L3 (-56, -28) -> (-56, -18)
  line L4 (-48.9, -28) -> (-56, -28)
extrude "Extrude59" cut sketch "Restore cam service path beneath compact rails" along normal blind 30.25
work_plane "WorkPlane60" AlongDistance 36 ExtraOffset 0
sketch "Restore cam service path beneath compact rails (1)" plane through (36, 0, 0) normal (1, 0, 0) x axis (0, 0, -1)
  line L1 (-48.9, 28) -> (-48.9, 18)
  line L2 (-56, 28) -> (-48.9, 28)
  line L3 (-56, 18) -> (-56, 28)
  line L4 (-48.9, 18) -> (-56, 18)
extrude "Extrude60" cut sketch "Restore cam service path beneath compact rails (1)" along normal blind 30.25
work_plane "WorkPlane66" AlongDistance 54.9 ExtraOffset 0
sketch "Support-free horizontal rail hole roof" plane through (0, 0, 54.9) normal (0, 0, 1) x axis (1, 0, 0)
  line L1 (-28.0908, -83.0908) -> (-28.0908, -86.9092)
  line L2 (-26.1816, -85) -> (-28.0908, -83.0908)
  line L3 (-28.0908, -86.9092) -> (-26.1816, -85)
extrude "Extrude66" cut sketch "Support-free horizontal rail hole roof" along normal blind 9.2
work_plane "WorkPlane67" AlongDistance 54.9 ExtraOffset 0
sketch "Support-free horizontal rail hole roof (1)" plane through (0, 0, 54.9) normal (0, 0, 1) x axis (1, 0, 0)
  line L1 (-28.0908, 86.9092) -> (-28.0908, 83.0908)
  line L2 (-26.1816, 85) -> (-28.0908, 86.9092)
  line L3 (-28.0908, 83.0908) -> (-26.1816, 85)
extrude "Extrude67" cut sketch "Support-free horizontal rail hole roof (1)" along normal blind 9.2
work_plane "WorkPlane61" AlongDistance 54.9 ExtraOffset 0
sketch "Support-free horizontal rail hole roof" plane through (0, 0, 54.9) normal (0, 0, 1) x axis (1, 0, 0)
  line L1 (31.9092, -83.0908) -> (31.9092, -86.9092)
  line L2 (33.8184, -85) -> (31.9092, -83.0908)
  line L3 (31.9092, -86.9092) -> (33.8184, -85)
extrude "Extrude61" cut sketch "Support-free horizontal rail hole roof" along normal blind 9.2
work_plane "WorkPlane62" AlongDistance 54.9 ExtraOffset 0
sketch "Support-free horizontal rail hole roof (1)" plane through (0, 0, 54.9) normal (0, 0, 1) x axis (1, 0, 0)
  line L1 (31.9092, 86.9092) -> (31.9092, 83.0908)
  line L2 (33.8184, 85) -> (31.9092, 86.9092)
  line L3 (31.9092, 83.0908) -> (33.8184, 85)
extrude "Extrude62" cut sketch "Support-free horizontal rail hole roof (1)" along normal blind 9.2
work_plane "WorkPlane14" AlongDistance 4 ExtraOffset 0
sketch "Reinforced roof over support-free pivot bore" plane through (4, 0, 0) normal (1, 0, 0) x axis (0, 0, -1)
  line L1 (-17.9, -29) -> (-17.9, -41)
  line L2 (-20, -29) -> (-17.9, -29)
  line L3 (-20, -41) -> (-20, -29)
  line L4 (-17.9, -41) -> (-20, -41)
extrude "Extrude14" add sketch "Reinforced roof over support-free pivot bore" along normal blind 3
work_plane "WorkPlane15" AlongDistance 4 ExtraOffset 0
sketch "Flat print foot below roller cheek" plane through (4, 0, 0) normal (1, 0, 0) x axis (0, 0, -1)
  line L1 (-6, 6) -> (-6, -6)
  line L2 (-12, 6) -> (-6, 6)
  line L3 (-12, -6) -> (-12, 6)
  line L4 (-6, -6) -> (-12, -6)
extrude "Extrude15" add sketch "Flat print foot below roller cheek" along normal blind 3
